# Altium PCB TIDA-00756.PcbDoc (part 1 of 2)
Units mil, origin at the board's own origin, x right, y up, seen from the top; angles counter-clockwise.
Board outline 4100 x 1700 mil, 4 copper layers (Top Layer, Signal Layer 1, Signal Layer 2, Bottom Layer), stack 43.668 mil thick; 130 components, 51 nets, 280 pads, 420 vias.
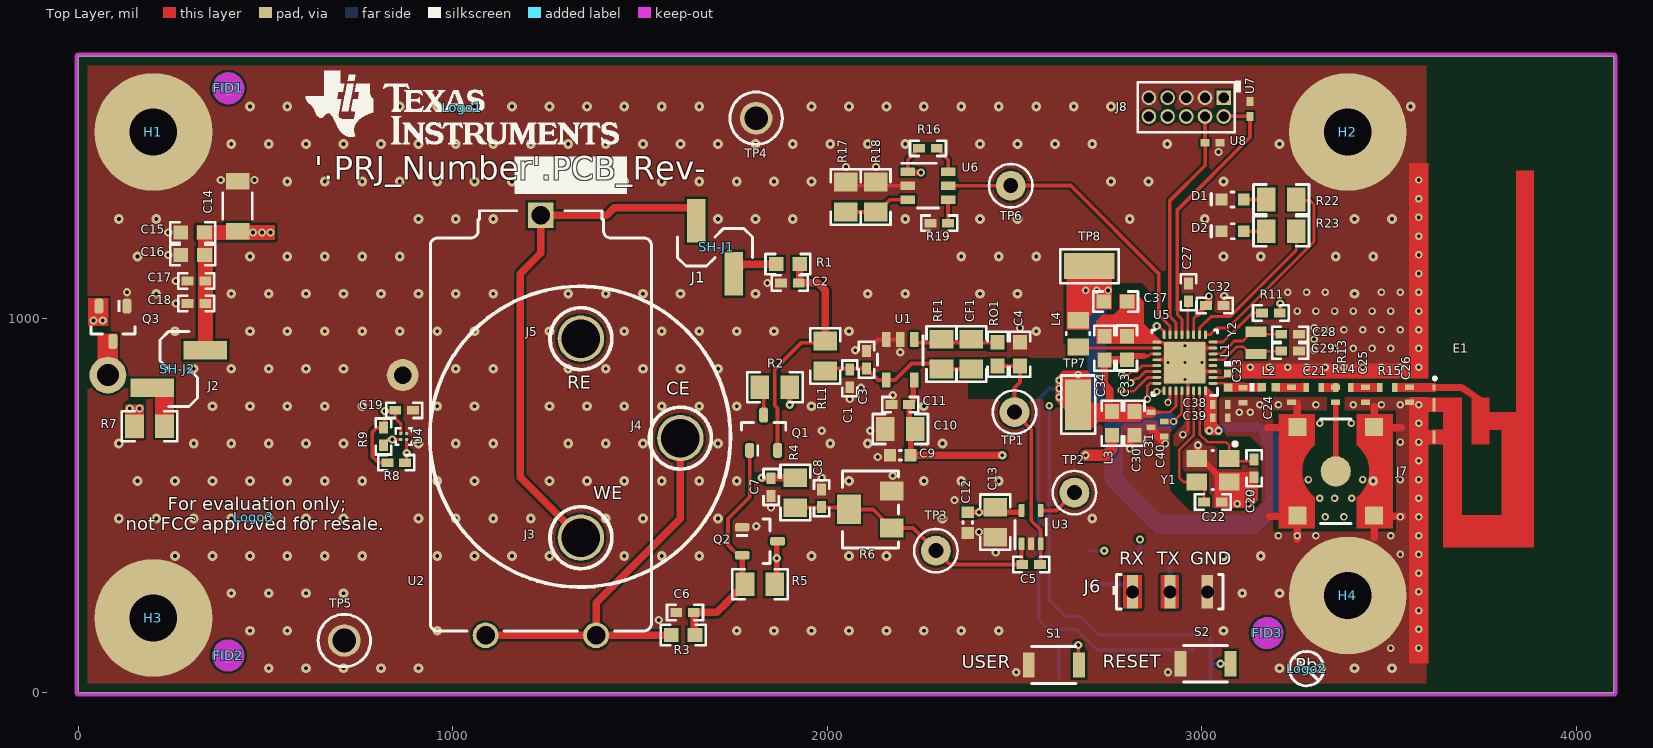
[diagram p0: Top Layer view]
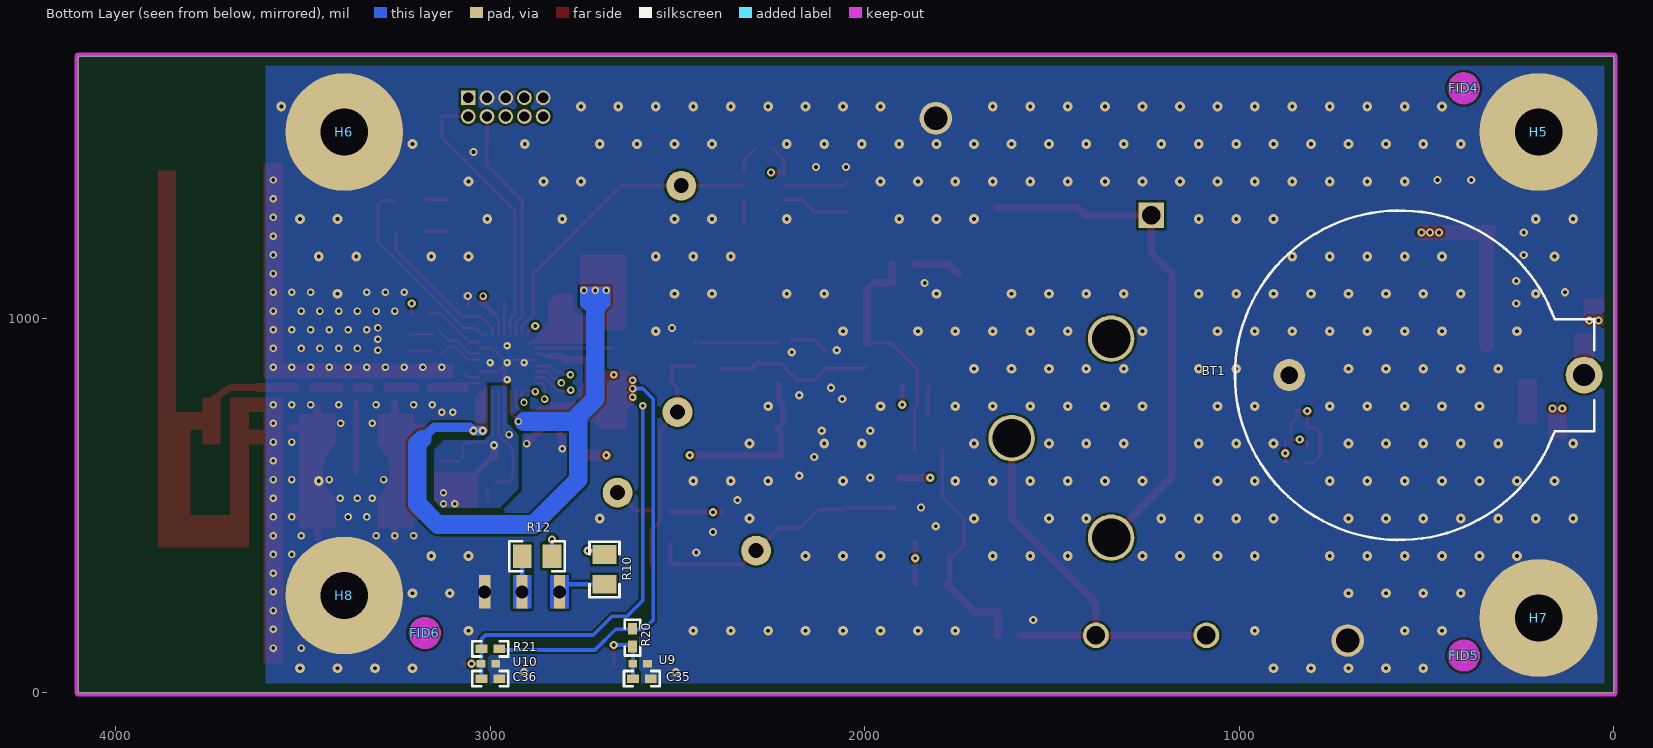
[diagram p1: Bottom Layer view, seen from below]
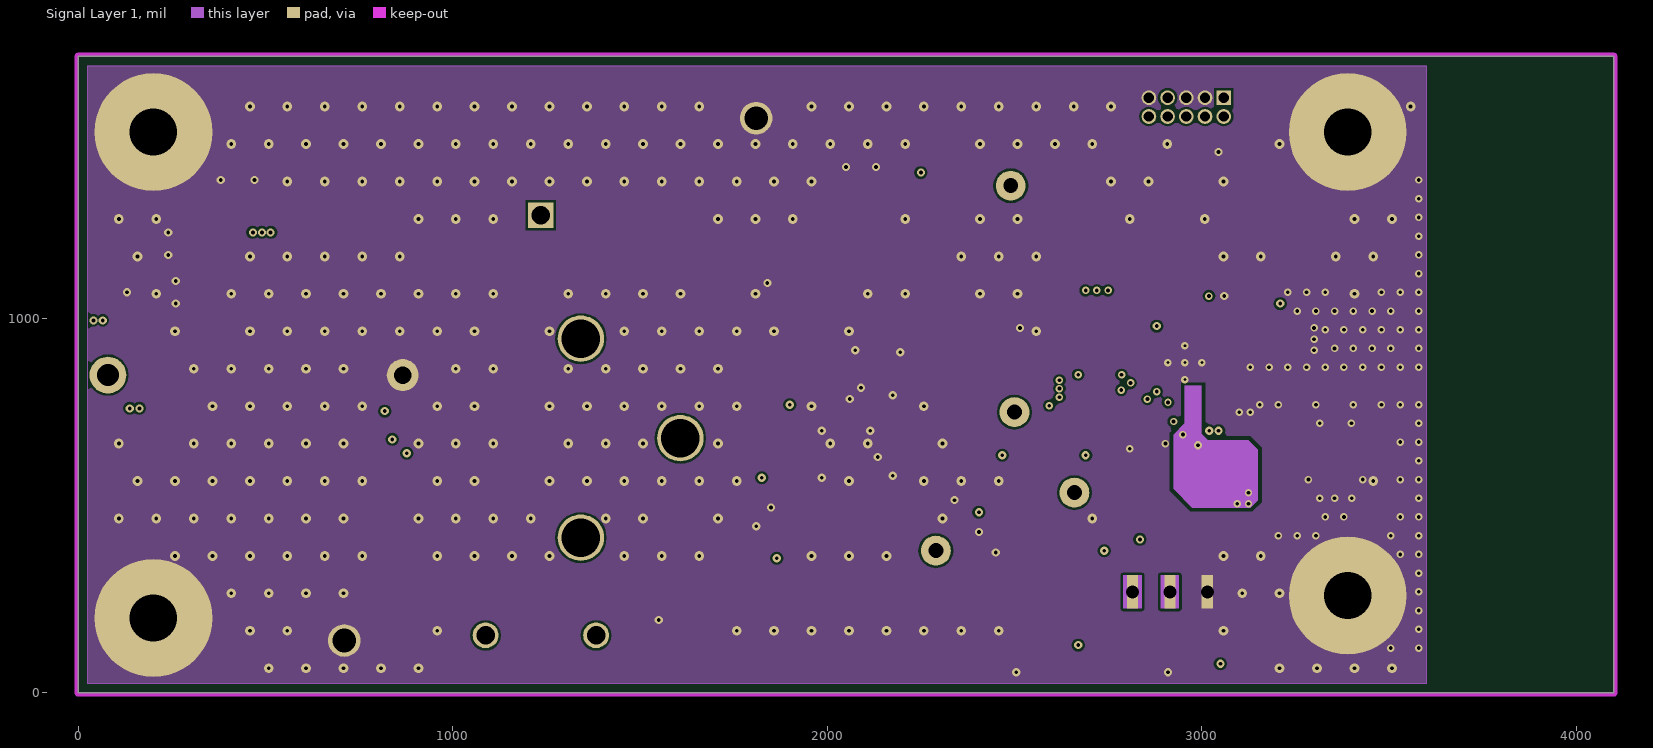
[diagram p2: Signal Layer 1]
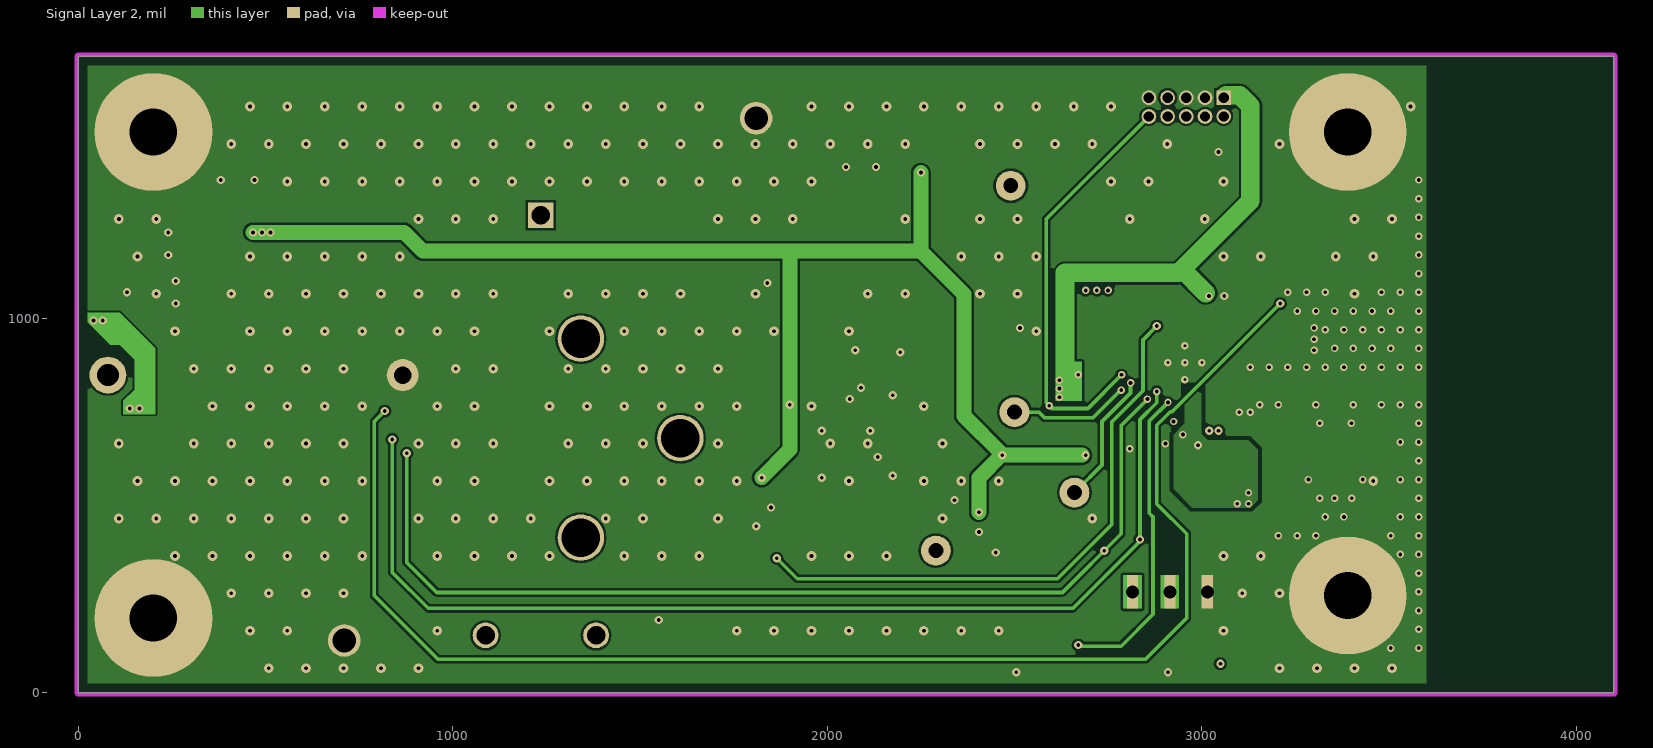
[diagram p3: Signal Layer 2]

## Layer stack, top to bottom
Top Solder: solder mask 0.4, Solder Resist, Dk 3.5
Top Layer: signal copper 1.417
Dielectric1: core 14, 370HR, Dk 4.2
Signal Layer 1: signal copper 1.417
Dielectric 2: prepreg 10, 370HR, Dk 4.2
Signal Layer 2: signal copper 1.417
Dielectric 3: core 14, 370HR, Dk 4.2
Bottom Layer: signal copper 1.417
Bottom Solder: solder mask 0.4, Solder Resist, Dk 3.5

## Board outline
0,0 4100,0 4100,1700 0,1700

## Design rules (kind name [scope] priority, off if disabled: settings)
AcuteAngle [All] p1: minimum=4.50000000000000E+0001 checktracksonly=FALSE
AssemblyTestPointUsage [All] p1: valid=2
BoardOutlineClearance BoardOutlineClearance_MountingHoles [OnCopper and InComponentClass('Mounting Holes')] p1: gap=40
BoardOutlineClearance BoardOutlineClearance_Poly [OnCopper and InPoly] p2: gap=25
BoardOutlineClearance [OnCopper and Not InComponentClass('Logo') and not InComponentClass('FiducialMark') and not InRegion(1000,500,4000,800)] p3: gap=25
Clearance Clearance_1 [IsRegion and InNet('GND')] p1: gap=6
Clearance Clearance_U4 [InComponent('U4')] p2: gap=6.6
Clearance Clearance_Keepouts [((IsTrack Or IsArc) And Not InPoly) And IsFree and IsKeepOut vs ((IsTrack Or IsArc) And Not InPoly) And IsFree and IsKeepOut] p3: gap=0
Clearance Clearance_Poly [InPolygon] p4: gap=12
Clearance [All] p5: gap=7.87
ComponentClearance ComponentClearance_sensor [InComponent('U1') vs InComponent('J2') or InComponent('J3')  or InComponent('J4')] p1: gap=0 collisioncheckmode=3 verticalgap=0 showdistances=FALSE
ComponentClearance ComponentClearance_RF [InComponent('R13') vs InComponent('R14')] p2: gap=0 collisioncheckmode=3 verticalgap=0 showdistances=FALSE
ComponentClearance ComponentClearance_MountingHoles_FiducialMarks [InComponentClass('Mounting Holes') vs InComponentClass('FiducialMark')] p3 off: gap=50 collisioncheckmode=3 verticalgap=10 showdistances=FALSE
ComponentClearance ComponentClearance_Shunt [InComponentClass('Header') vs InComponentClass('Shunt')] p4: gap=0 collisioncheckmode=3 verticalgap=0 showdistances=FALSE
ComponentClearance ComponentClearance_Logo [InComponentClass('Logo')] p5: gap=0 collisioncheckmode=3 verticalgap=0 showdistances=FALSE
ComponentClearance ComponentClearance_ScrewToNut [(HasFootprint('NY PMS 440 0025 PH')) vs (HasFootprint('Keystone_1902C'))] p6: gap=5 collisioncheckmode=3 verticalgap=10 showdistances=FALSE
ComponentClearance ComponentClearance_MountingHoles [InComponentClass('Mounting Holes')] p7 off: gap=250 collisioncheckmode=3 verticalgap=100000 showdistances=FALSE
ComponentClearance ComponentClearance_SmallPassives [HasFootprint('0201*') or HasFootprint('0402*') or HasFootprint('0508') or HasFootprint('0603*') or HasFootprint('0612') or HasFootprint('0805*') or HasFootprint('0815*') or HasFootprint('0830*') or HasFootprint('1206*') or HasFootprint('1210*') or HasFootprint('1808*') or HasFootprint('1812*') or HasFootprint('1825*') or HasFootprint('2010*') or HasFootprint('2220*') or HasFootprint('2225*') or HasFootprint('2512*') or HasFootprint('2728*') or HasFootprint('3518*') vs HasFootprint('0201*') or HasFootprint('0402*') or HasFootprint('0508') or HasFootprint('0603*') or HasFootprint('0612') or HasFootprint('0805*') or HasFootprint('0815*') or HasFootprint('0830*') or HasFootprint('1206*') or HasFootprint('1210*') or HasFootprint('1808*') or HasFootprint('1812*') or HasFootprint('1825*') or HasFootprint('2010*') or HasFootprint('2220*') or HasFootprint('2225*') or HasFootprint('2512*') or HasFootprint('2728*') or HasFootprint('3518*')] p8: gap=5 collisioncheckmode=3 verticalgap=5 showdistances=FALSE
ComponentClearance ComponentClearance_THtoSMT [IsThruComponent vs IsSMTComponent] p9: gap=5 collisioncheckmode=3 verticalgap=5 showdistances=FALSE
ComponentClearance ComponentClearance_THtoTH [IsThruComponent vs IsThruComponent] p10: gap=5 collisioncheckmode=3 verticalgap=5 showdistances=FALSE
ComponentClearance [All] p11: gap=5 collisioncheckmode=3 verticalgap=5 showdistances=FALSE
DiffPairsRouting [All] p1: maxlimit=100 minlimit=10 mostfreqgap=10 toplayer_minwidth=15 toplayer_maxwidth=15 toplayer_prefwidth=15 midlayer1_minwidth=15 midlayer1_maxwidth=15 midlayer1_prefwidth=15 midlayer2_minwidth=15 midlayer2_maxwidth=15 midlayer2_prefwidth=15 bottomlayer_minwidth=15 bottomlayer_maxwidth=15 bottomlayer_prefwidth=15 maxuncoupledlength=1000
FabricationTestPointUsage TestPointUsage [All] p1: valid=2 allowmultiple=FALSE
FabricationTestpoint Testpoint [All] p1: side=3 testpointundercomponent=TRUE minsize=40 maxsize=100 preferedsize=60 minholesize=0 maxholesize=40 preferedholesize=32 testpointgrid=1 allowsidetop=TRUE allowsidebottom=TRUE usegrid=TRUE gridtolerance=0.01
FanoutControl Fanout_LCC [IsLCC] p1: bgadir=Out bgaviamode=Centered fanoutstyle=Auto fanoutdirection=Alternating viagrid=1 // Fanout_LCC (Default Rule)
FanoutControl Fanout_BGA [IsBGA] p2: bgadir=Out bgaviamode=Centered fanoutstyle=Auto fanoutdirection=Alternating viagrid=1 // Fanout_BGA (Default Rule)
FanoutControl Fanout_Default [All] p4: bgadir=Out bgaviamode=Centered fanoutstyle=Auto fanoutdirection=Alternating viagrid=1 // Fanout_Default (Default Rule)
FanoutControl Fanout_Small [(CompPinCount < 5)] p5: bgadir=Out bgaviamode=Centered fanoutstyle=Auto fanoutdirection=OutThenIn viagrid=1 // Fanout_Small (Default Rule)
HoleSize [All] p1: absolutevalues=TRUE maxlimit=251 minlimit=7.87 maxpercent=80.000 minpercent=20.000
MinimumAnnularRing MinimumAnnularRing_1 [InComponent('J6')] p1: minimumring=0
MinimumAnnularRing MinimumAnnularRing_ThermalPadVias [IsVia and InAnyComponent] p2: minimumring=5.91
MinimumAnnularRing [All] p3: minimumring=5
MinimumSolderMaskSliver MinimumSolderMaskSliver_Logo [InComponentClass('Logo') vs InComponentClass('Logo')] p1: minsoldermaskwidth=0.7
MinimumSolderMaskSliver [All] p2: minsoldermaskwidth=3.94
PlaneConnect [All] p1: planeconnectstyle=Relief reliefexpansion=10 reliefentries=4 reliefconductorwidth=10 reliefairgap=10
PolygonConnect PolygonConnect_TR [incomponent('Q1') or incomponent('J5')] p1: connectstyle=Relief reliefconductorwidth=12 reliefentries=4 polygonreliefangle="90 Angle" airgapwidth=10
PolygonConnect [All] p2: connectstyle=Direct reliefconductorwidth=10 reliefentries=4 polygonreliefangle="90 Angle" airgapwidth=10
RoutingVias ThermalPadVias [IsVia and InAnyComponent] p1: holewidth=7.87 width=19.68 viastyle="Through Hole" minholewidth=7.87 minwidth=19.68 maxholewidth=12.99 maxwidth=23.62
RoutingVias [All] p2: holewidth=16 width=26 viastyle="Through Hole" minholewidth=7.87 minwidth=20 maxholewidth=40 maxwidth=65
SilkToBoardRegionClearance [Not ((IsComment or IsDesignator) And (Hide <> 'False')) and not InRegion(1000,500,4000,800)] p1:
SilkToSilkClearance SilkToSilkClearance_Pb-FreeLogo [(HasFootprint('Pb-Free_Overlay_Medium') OR HasFootprint('Pb-Free_Overlay_Small')) vs (HasFootprint('Pb-Free_Overlay_Medium') OR HasFootprint('Pb-Free_Overlay_Small'))] p1: silktosilkclearance=0
SilkToSilkClearance [All] p2: silktosilkclearance=4
SilkToSolderMaskClearance SilkToComponentPadClearance [IsPad and InAnycomponent] p1: minsilkscreentomaskgap=5 clearancetoexposedcopper=TRUE
SilkToSolderMaskClearance "Silk to Solder Mask Opening" [All] p2: minsilkscreentomaskgap=4 clearancetoexposedcopper=FALSE
SolderMaskExpansion [All] p1: expansion=1.8
Width [All] p1: maxlimit=100 minlimit=6 preferedwidth=10 checkconnectedcopper=TRUE
15 further rules are at their usual default settings.

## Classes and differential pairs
component class Shunt: SH-J1 SH-J2
component class TIDA-00756_MCU: C19 C20 C21 C22 C23 C24 C25 C26 C27 C28 C29 C30 C31 C32 C33 C34 C35 C36 C37 C38 C39 C40 D1 D2 E1 J6 J7 J8 L1 L2 L3 L4 R8 R9 R10 R11 R12 R13 R14 R15 R16 R17 R18 R19 R20 R21 R22 R23 S1 S2 TP6 TP7 TP8 U4 U5 U6 U7 U8 U9 U10 Y1 Y2
component class TIDA-00756_CO_Sensor: BT1 C1 C2 C3 C4 C5 C6 C7 C8 C9 C10 C11 C12 C13 C14 C15 C16 C17 C18 CF1 J1 J2 J3 J4 J5 Q1 Q2 Q3 R1 R2 R3 R4 R5 R6 R7 RF1 RL1 RO1 TP1 TP2 TP3 TP4 TP5 U1 U2 U3
component class Header: J1 J2 J6 J8
component class "Mounting Holes": H1 H2 H3 H4
component class Logo: Logo1
component class TIDA-00756_Hardware: FID1 FID2 FID3 FID4 FID5 FID6 H1 H2 H3 H4 H5 H6 H7 H8 Logo1 Logo2 Logo3 SH-J1 SH-J2 ZZ2 ZZ3 ZZ4
component class FiducialMark: FID1 FID2 FID3 FID4 FID5 FID6
component class AssemblyNote: ZZ2 ZZ3 ZZ4

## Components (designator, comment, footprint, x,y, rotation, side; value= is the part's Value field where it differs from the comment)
BT1 "BS-7" BAT_BS-7 472.44,848.98 r0 bottom locked
C1 "CC0402JRNPO9BN150" 0402 2060,840 r90 top
C2 "CC0402JRNPO9BN150" 0402 1900,1095 r180 top
C3 "CC0402JRNPO9BN150" 0402 2105,890 r90 top
C4 "C1608X5R1E105K080AC" 0603 2515,905 r90 top
C5 "C0402C102J3RACTU" 0402 2544.5,343 r180 top
C6 "CC0402JRNPO9BN150" 0402 1620,215 r180 top
C7 "CC0402JRNPO9BN150" 0402 1850,550 r270 top
C8 "C1005X7R1H104K" 0402 1985,520 r90 top
C9 "C0603C104K8RACTU" 0603L 2195,635 r0 top
C10 "C2012X5R0J106M" 0805_HV 2195,705 r0 top
C11 "CC0402JRNPO9BN150" 0402 2195,770 r180 top
C12 "C0603C104K8RACTU" 0603L 2375,455 r90 top
C13 "C2012X5R0J106M" 0805_HV 2449,456 r90 top
C14 "C3216X5R1A107M160AC" 1206_190 425,1300 r90 top
C15 "C1608X5R0J106M" 0603 305,1230 r180 top
C16 "C1608X7R1C105K" 0603 305,1170 r180 top
C17 "C1005X7R1H104K050BB" 0402 315,1100 r180 top
C18 "C1005X7R1C103K050BA" 0402 315,1040 r180 top
C19 "GRM155R71C103KA01D" 0402 870,755 r0 top
C20 "GRM1555C1E120JA01D" 0402 3140,600 r90 top
C21 "GRM1555C1H120JA01D" 0402S 3299,816.3 r180 top
C22 "GRM1555C1E120JA01D" 0402 3030,510 r180 top
C23 "GRM1555C1H1R2BA01D" 0402S 3110,795 r270 top
C24 "GRM1555C1H1R2BA01D" 0402S 3240,796.3 r270 top
C25 "Used in BOM report" 0402S 3437,796.3 r90 top
C26 "Used in BOM report" 0402S 3555,796.3 r90 top
C27 "GRM155R61A105KE15D" 0402 2965,1070 r90 top
C28 "GRM1555C1E120JA01D" 0402 3236,958 r0 top
C29 "GRM1555C1E120JA01D" 0402 3236,913 r0 top
C30 "Used in BOM report" 0603 2820,720 r270 top
C31 "GRM155R70J104KA01D" 0402S 2865,730 r270 top
C32 "GRM155R70J104KA01D" 0402 3035,1035 r0 top
C33 "GRM188R60J106ME47D" 0603 2800,921.31 r270 top
C34 "GRM188R71E104KA01D" 0603 2740,921 r270 top
C35 "C1005X7R1H222K" 0402 2595,38 r0 bottom
C36 "C1005X7R1H222K" 0402 3000,38 r0 bottom
C37 "GRM188R60J106ME47D" 0603 2770,1045 r180 top
C38 "GRM155R70J104KA01D" 0402S 3050,770 r0 top
C39 "GRM155R70J104KA01D" 0402S 3050,735 r0 top
C40 "Used in BOM report" 0402S 2900,705 r270 top
CF1 "08053C104KAT2A" 0805_HV 2385,905 r270 top
D1 "LS L29K-G1J2-1-Z" "LS L29K_Red" 3082.56,1317.87 r180 top
D2 "LY L29K-H1K2-26-Z" "LY L29K_Yellow" 3082.56,1232.87 r180 top
E1 "ANTENNA_DN007A" ANTENNA_DN007A 3620.31,816.03 r270 top net-tie
FID1 "Fiducial" Fiducial10-20 400,1615 r0 top
FID2 "Fiducial" Fiducial10-20 400,100 r0 top
FID3 "Fiducial" Fiducial10-20 3175,160 r0 top
FID4 "Fiducial" Fiducial10-20 400,1615 r90 bottom
FID5 "Fiducial" Fiducial10-20 400,100 r90 bottom
FID6 "Fiducial" Fiducial10-20 3175,160 r90 bottom
H1 "NY PMS 440 0025 PH" "NY PMS 440 0025 PH" 200,1497.95 r0 top locked
H2 "NY PMS 440 0025 PH" "NY PMS 440 0025 PH" 3390,1497.95 r0 top locked
H3 "NY PMS 440 0025 PH" "NY PMS 440 0025 PH" 200,200 r0 top locked
H4 "NY PMS 440 0025 PH" "NY PMS 440 0025 PH" 3390,260 r0 top locked
H5 "1902C" Keystone_1902C 200,1497.95 r180 bottom locked
H6 "1902C" Keystone_1902C 3390,1497.95 r180 bottom locked
H7 "1902C" Keystone_1902C 200,200 r180 bottom locked
H8 "1902C" Keystone_1902C 3390,260 r180 bottom locked
J1 "87898-0204" Molex_87898-0204 1700,1190 r0 top
J2 "87898-0204" Molex_87898-0204 267.72,865 r90 top
J3 "2-50871-2" TE_2-50871-2 1341.93,414.68 r0 top
J4 "2-50871-2" TE_2-50871-2 1607.68,680.43 r0 top
J5 "2-50871-2" TE_2-50871-2 1341.93,946.18 r270 top
J6 "5-146280-3" TE_5-146280-3 2915,270 r0 top
J7 "CONSMA001-SMD-G" Linx_CONSMA001-SMD-G 3358,592 r0 top
J8 "GRPB052VWVN-RC" CONN_GRPB052VWVN-RC 2958.94,1564.69 r180 top
L1 "LQG15HS15NJ02D" IND_LQG15H 3071,835 r270 top
L2 "LQG15HS2N0S02D" IND_LQG15H 3179,816.3 r0 top
L3 "BLM18HE152SN1D" 0603 2760,720 r90 top
L4 "CKS2125100M-T" 0805_145 2670,960 r90 top
Logo1 "Texas Instruments" TI_Stacked_Overlay_Small 1025,1563 r0 top
Logo2 "Pb-Free Symbol" Pb-Free_Overlay_Small 3280,65 r0 top
Logo3 "FCC disclaimer" FCC_disclaimer_stacked 468,469 r0 top
Q1 "MMBFJ270" SOT-23 1830,695 r90 top
Q2 "MMBFJ270" SOT-23 1820,405 r0 top
Q3 "SI2323DS" SOT-23 92,986 r270 top
R1 "CRCW06030000Z0EA" 0603 1895,1145 r0 top
R2 "CRCW08052M00JNEA" 0805_HV 1860,816.12 r180 top
R3 "CRCW06030000Z0EA" 0603 1615,155 r0 top
R4 "ERJ-6GEYK226V" 0805_HV 1915,535 r90 top
R5 "CRCW08052M55FKEA" 0805_HV 1820,290 r0 top
R6 "3224W-1-205E" TRIM_3224W 2115,490 r180 top
R7 "CRCW08050000Z0EA" 0805_HV 190,712 r0 top
R8 "CRCW04024K75FKED" 0402 848.7,614.92 r180 top
R9 "CRCW04024K75FKED" 0402 815,685 r90 top
R10 "CRCW08050000Z0EA" 0805_HV 2695,330 r90 bottom
R11 "CRCW04020000Z0ED" 0402 3185,1015 r0 top
R12 "CRCW08050000Z0EA" 0805_HV 2875,365 r180 bottom
R13 "CRCW04020000Z0ED" 0402S 3358,796 r270 top
R14 "CRCW04020000Z0ED" 0402S 3378,816 r0 top
R15 "CRCW04020000Z0ED" 0402S 3496,816.3 r0 top
R16 "CRCW04020000Z0ED" 0402 2268.94,1454.69 r180 top
R17 "ERJ-6ENF5492V" 0805_HV 2048.94,1324.69 r270 top
R18 "ERJ-6ENF1963V" 0805_HV 2128.94,1324.69 r90 top
R19 "CRCW040210K0FKED" 0402 2298.94,1254.69 r0 top
R20 "CRCW040247K5FKED" 0402 2620,148 r90 bottom
R21 "CRCW040247K5FKED" 0402 3000,118 r180 bottom
R22 "CRCW0805442RFKEA" 0805_HV 3212.44,1317.87 r180 top
R23 "CRCW0805487RFKEA" 0805_HV 3212.44,1232.87 r180 top
RF1 "CRCW08051M78FKEA" 0805_HV 2305,905 r90 top
RL1 "CRCW08050000Z0EA" 0805_HV 1995,900 r270 top
RO1 "CRCW060349K9FKEA" 0603 2455,905 r270 top
S1 "B3U-1000P" SW_B3U-1000P 2605,75 r0 top
S2 "B3U-1000P" SW_B3U-1000P 3010,78 r0 top
SH-J1 "969102-0000-DA" SNT-100-BK-G 1705,1190 r0 top
SH-J2 "969102-0000-DA" SNT-100-BK-G 265,865 r90 top
TP1 "5004" Keystone5004 2500,750 r180 top
TP2 "5004" Keystone5004 2660,535 r180 top
TP3 "5004" Keystone5004 2290,380 r0 top
TP4 "5011" Keystone5011 1810,1535 r0 top
TP5 "5011" Keystone5011 710,140 r0 top
TP6 "5004" Keystone5004 2490,1354.69 r0 top
TP7 "5015" Testpoint_Keystone_Miniature 2670,770 r90 top
TP8 "5015" Testpoint_Keystone_Miniature 2700,1140 r0 top
U1 "LPV811DBVR" DBV0005A_N 2195,890 r270 top
U2 "TGS5342" FIGARO_TGS5342 1235,715 r270 top
U3 "TLV3691IDCKR" DCK0005A_N 2544.5,443 r90 top
U4 "TMP103AYFFR" YFF0004AAAA 868.7,684.92 r0 top
U5 "CC2650F128RSMR" RSM0032B 2955,882 r180 top
U6 "TPL5111DDCR" DDC0006A_N 2268.94,1354.69 r0 top
U7 "TPD1E10B06DPYR" DPY0002A 3128.94,1559.69 r90 top
U8 "TPD1E10B06DPYR" DPY0002A 3028.94,1469.69 r0 top
U9 "TPD1E10B06DPYR" DPY0002A 2600,78 r180 bottom
U10 "TPD1E10B06DPYR" DPY0002A 3005,78 r180 bottom
Y1 "TSX-3225 24.0000MF20G-AC3" EPSON_TSX-3225 3030,595 r270 top
Y2 "FC-12M 32.7680KA-A3" Epson_FC-12M 3145,935 r90 top
ZZ2 "These assemblies are ESD sensitive, ESD precautions shall be observed." AssemblyNote 185,3829.11 r0 top
ZZ3 "These assemblies must be clean and free from flux and all contaminants. Use of no clean flux is not acceptable." AssemblyNote 185,3740.56 r0 top
ZZ4 "These assemblies must comply with workmanship standards IPC-A-610 Class 2, unless otherwise specified." AssemblyNote 185,3652 r0 top

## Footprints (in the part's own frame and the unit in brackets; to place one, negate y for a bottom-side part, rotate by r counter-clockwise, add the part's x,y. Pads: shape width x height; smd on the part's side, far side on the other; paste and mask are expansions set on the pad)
0402 [mm] "0402 from SM-752 data"
  rect 0.8x0.6 smd: 1(-0.6,0) 2(0.6,0)
  silkscreen extent -1.22,-0.52 1.22,0.52, body extent -0.55,-0.3 0.55,0.3, height 0.6
0402S [mil] "Based on C0402S footprint from PADS legacy"
  rect 15x24 smd: 1(-20,0) 2(20,0)
  body extent -22,-12 22,12, height 24
0603 [mm] "0603 from SM-752 data"
  rect 1x0.95 smd: 1(-0.8,0) 2(0.8,0)
  silkscreen extent -1.52,-0.69 1.52,0.69, body extent -0.87,-0.47 0.87,0.47, height 1
0603L [mm] "0603 from SM-752 data"
  rect 0.8x0.85 smd: 1(-0.7,0) 2(0.7,0)
  silkscreen extent -0.07,-0.33 0.07,0.33, body extent -0.87,-0.47 0.87,0.47, height 1
0805_145 [mm] "0805 / 1.45mm height"
  rect 1.15x1.45 smd: 1(-0.9,0) 2(0.9,0)
  silkscreen extent -0.1,-0.8 0.1,0.8, body extent -1.1,-0.72 1.1,0.72, height 1.45
0805_HV [mil] "0805 with 30mil clearance between pads"
  rect 50x63 smd: 1(-40,0) 2(40,0)
  silkscreen extent -74,-40 74,40, body extent -43,-29 43,29, height 57
1206_190 [mm] "1206_190"
  rect 1.1x1.6 smd: 1(-1.7,0) 2(1.7,0)
  silkscreen extent -0.9,-1 0.9,1, body extent -1.75,-0.95 1.75,0.95, height 1.9
ANTENNA_DN007A [mm] "SMD, 3-Leads"
  rect 0.4x0.2 smd paste-2 mask-2: 1(0,0)
  rect 0.9x0.2 smd paste-2 mask-2: 2(1.18,-0.01) 3(3.37,0)
  Top Layer region: 10.84,0.63 10.84,6.775 -14.715,6.775 -14.715,5.59 1.685,5.59 1.685,3.765 0.685,3.765 0.685,3.271 -0.225,1.951 -0.225,-0.11 0.21,-0.11 0.21,1.816 0.737,2.58 3.86,2.58 3.86,3.765 2.86,3.765 2.86,4.59 8.685,4.59 8.685,1.895 0.685,1.895 0.685,-0.11 1.66,-0.11 1.66,0.63 2.885,0.63 2.885,-0.11 3.86,-0.11 3.86,0.63
  silkscreen extent -0.71,-0.04 -0.51,0.16
AssemblyNote [mil] "Assembly Note"
BAT_BS-7 [mm] "Memory Protection Devices CR2032 battery holder"
  round 2.5 hole 1.5: 1(-10,0)
  round 2.17 hole 1.181: 2(10,0)
  silkscreen extent -10.7,-11.16 13.68,11.18, body extent -10.69,-11.17 13.7,11.17, height 9.02
CONN_GRPB052VWVN-RC [mm] "SULLINS"
  rect 1x1 hole 0.7 mask+0.08: 1(-2.54,-0.635)
  round 1 hole 0.7 mask+0.08: 2(-2.54,0.635) 3(-1.27,-0.635) 4(-1.27,0.635) 5(0,-0.635) 6(0,0.635) 7(1.27,-0.635) 8(1.27,0.635) 9(2.54,-0.635) 10(2.54,0.635)
  silkscreen extent -3.7,-1.8 3.3,1.7, body extent -3.17,-1.7 3.17,1.7, height 4
DBV0005A_N [mm] "SOT23, 5-Leads, Body 2.9x1.6mm, Pitch 0.95mm, Lead Span 2.8mm, IPC Medium Density"
  rrect17% 1x0.6 smd: 1(-1.375,0.95) 2(-1.375,0) 3(-1.375,-0.95) 4(1.375,-0.95) 5(1.375,0.95)
  silkscreen extent -1.63,-1.55 0.38,1.55, body extent -1.42,-1.46 1.42,1.46, height 1.09
DCK0005A_N [mm] "SOT353, 5-Leads, Body 2x1.3mm, Pitch 0.65mm, Lead Span 2.1mm, IPC Medium Density"
  rrect25% 0.85x0.4 smd: 1(-1.125,0.65) 2(-1.125,0) 3(-1.125,-0.65) 4(1.125,-0.65) 5(1.125,0.65)
  silkscreen extent -1.48,-1.02 0.55,1.1, body extent -1.14,-1 1.14,1, height 0.95
DDC0006A_N [mm]
  rrect17% 1x0.6 smd: 1(-1.375,0.95) 2(-1.375,0) 3(-1.375,-0.95) 4(1.375,-0.95) 5(1.375,0) 6(1.375,0.95)
  silkscreen extent -1.75,-1.52 0.7,1.53, body extent -1.43,-1.48 1.43,1.49, height 0.92
DPY0002A [mm] "R-PX2SON-N2"
  rect 0.6x0.5 smd: 1(-0.5,0) 2(0.5,0)
  body extent -0.55,-0.35 0.55,0.35, height 0.4
Epson_FC-12M [mm] "Epson"
  rect 0.7x1.4 smd: 1(-0.75,0) 2(0.75,0)
  body extent -1.05,-0.63 1.05,0.63, height 0.6
EPSON_TSX-3225 [mm] "SMD, 4-Leads, Body 2.65x3.35mm, Height 0.6mm"
  rect 1.15x1.4 smd: 1(-0.8,1.1) 2(-0.8,-1.1) 3(0.8,-1.1) 4(0.8,1.1)
  silkscreen extent -1.9,-0.05 1.33,1.63, body extent -1.33,-1.68 1.33,1.68, height 0.61
FCC_disclaimer_stacked [mil]
Fiducial10-20 [mm]
  round 1 smd mask+0.5: 1(0,0)
  Top Layer keep-out circle w1.178: c0,0 r0.5
FIGARO_TGS5342 [mm] "TH, 3-Leads, Body 15x27.9mm, Pin Spacing 25.5mm"
  rect 1.75x1.75 hole 1.25: 1(-14.25,0)
  round 1.75 hole 1.25: 2(14.25,-3.75) 2(14.25,3.75)
  silkscreen extent -14.55,-7.5 13.95,7.5, body extent -14.55,-7.5 14.55,7.5, height 16.9
IND_LQG15H [mm] "MuRata"
  rect 0.55x0.6 smd: 1(-0.475,0) 2(0.475,0)
  silkscreen extent -1.3,-0.3 -0.95,0.3, body extent -0.52,-0.27 0.52,0.27, height 0.55
Keystone5004 [mil] "For Keystone 500x miniature loop terminals"
  round 80 hole 40: 1(0,0)
  silkscreen extent -58,-58 58,58, body extent -49,-49 49,49, height 182
Keystone5011 [mil] "Keystone Multipurpose loops"
  round 87 hole 63: 1(0,0)
  silkscreen extent -70,-70 70,70, body extent -63,-63 63,62, height 319
Keystone_1902C [mil] "Hex Standoff, 4-40 threaded, nylon"
  body extent -145,-126 146,126, height 501
Linx_CONSMA001-SMD-G [mm] "SMD, 5-Leads, Body 7x7mm, Height 10.5mm"
  round 2.05 smd: 1(0,0)
  rect 1.2x1.2 smd: 2(-2.6,-3) 3(2.6,-3) 4(2.6,3) 5(-2.6,3)
  Top Layer region: 3.88,-3.88 1.44,-3.88 1.44,-1.761 1.448,-1.761 2.062,-0.974 2.28,0 2.062,0.974 1.448,1.761 1.448,1.761 1.44,1.761 1.44,3.88 3.88,3.88
  Top Layer region: -3.88,-3.88 -1.44,-3.88 -1.44,-1.761 -1.448,-1.761 -2.062,-0.974 -2.28,0 -2.062,0.974 -1.448,1.761 -1.448,1.761 -1.44,1.761 -1.44,3.88 -3.88,3.88
  silkscreen extent -1.04,-3.55 1.04,3.55, body extent -3.55,-3.55 3.55,3.55, height 10.5
"LS L29K_Red" [mm] "SMD, 2-Leads, Body 1.3x0.8mm"
  rect 0.8x0.8 smd paste-0.4: 1(-0.75,0) 2(0.75,0)
  silkscreen extent -0.1,-0.5 1.45,0.5, body extent -0.9,-0.45 0.9,0.45, height 0.67
"LY L29K_Yellow" [mm] "OSRAM"
  rect 0.8x0.8 smd paste-0.4: 1(-0.75,0) 2(0.75,0)
  silkscreen extent -0.1,-0.5 1.45,0.5, body extent -0.9,-0.45 0.9,0.45, height 0.67
Molex_87898-0204 [mm] "Header, 2.54 mm, 2x1, R/A, SMT"
  rect 1.27x2.96 smd: 1(-1.27,1.8) 2(1.27,-1.8)
  silkscreen extent -2.54,-1.27 2.54,1.27, body extent -2.54,-2.4 2.54,2.4, height 9.65
"NY PMS 440 0025 PH" [mm] "4-40 nylon screw and mounting hole"
  round 8 hole 3.2: 1(0,0)
  body extent -3.3,-3.3 3.3,3.3, height 2.69
Pb-Free_Overlay_Small [mil]
  silkscreen extent -46,-46 46,46
RSM0032B [mm] "QFN, 32-Leads, Body 4x4mm, Pitch 0.4mm, Thermal Pad 2.8x2.8mm, TI Recommended"
  oval 0.6x0.2 smd: 1(-1.9,1.4) 2(-1.9,1) 3(-1.9,0.6) 4(-1.9,0.2) 5(-1.9,-0.2) 6(-1.9,-0.6) 7(-1.9,-1) 8(-1.9,-1.4) 17(1.9,-1.4) 18(1.9,-1) 19(1.9,-0.6) 20(1.9,-0.2) 21(1.9,0.2) 22(1.9,0.6) 23(1.9,1) 24(1.9,1.4)
  oval 0.2x0.6 smd: 9(-1.4,-1.9) 10(-1,-1.9) 11(-0.6,-1.9) 12(-0.2,-1.9) 13(0.2,-1.9) 14(0.6,-1.9) 15(1,-1.9) 16(1.4,-1.9) 25(1.4,1.9) 26(1,1.9) 27(0.6,1.9) 28(0.2,1.9) 29(-0.2,1.9) 30(-0.6,1.9) 31(-1,1.9) 32(-1.4,1.9)
  rect 2.8x2.8 smd paste-1.4: 33(0,0)
  silkscreen extent -2.23,-2.23 2.23,2.23, body extent -2.07,-2.07 2.08,2.08, height 1.01
SNT-100-BK-G [mil] "Samtec STEP model"
  round 1 on Mech3: 0(0,0)
  body extent -100,-50 100,50, height 344
SOT-23 [mm] "SOT23, 3-Leads, Body 2.9x1.3mm, Pitch 0.95mm, Lead Span 2.5mm, IPC Medium Density"
  rrect50% 1x0.6 smd: 1(-1.2,0.95) 2(-1.2,-0.95) 3(1.2,0)
  silkscreen extent -1.63,-1.5 0.7,1.5, body extent -1.16,-1.45 1.21,1.45, height 1
SW_B3U-1000P [mm] "OMRON"
  rect 0.8x1.7 smd: 1(-1.7,0) 2(1.7,0)
  silkscreen extent -1.5,-1.25 1.5,1.25, body extent -1.5,-1.25 1.5,1.25, height 1.75
TE_2-50871-2 [mm] "CONN SOCKET RCPT .056-.065 30AU, TH"
  round 3.15 hole 2.62: 1(0,0)
  silkscreen extent -2.1,-2.1 2.1,2.1, body extent -1.46,-1.46 1.46,1.46, height 0.46
TE_5-146280-3 [mm] "Header, 2.54mm, 3x1, TH"
  rect 0.76x2.29 hole 0.89: 1(-2.54,0) 2(0,0) 3(2.54,0)
  silkscreen extent -3.9,-1.17 3.61,1.17, body extent -3.61,-1.17 3.61,1.17, height 8.13
Testpoint_Keystone_Miniature [mil] "Miniature SMT test point"
  rect 135x70 smd: 1(0,0)
  silkscreen extent -78,-46 78,45, body extent -52,-20 52,20, height 61
TI_Stacked_Overlay_Small [mil]
  silkscreen extent -418,-98 418,98
TRIM_3224W [mm] "BOURNS"
  rect 1.6x1.3 smd: 1(-1.45,1.25) 3(-1.45,-1.25)
  rect 1.6x2 smd: 2(1.45,0)
  silkscreen extent -1.9,-2.6 1.9,2.6, body extent -1.8,-2.5 1.8,2.5, height 5.31
YFF0004AAAA [mm] "TI DSBGA 0.790x0.790mm"
  round 0.23 smd paste-0.13 mask+0.03: A1(-0.2,0.2) A2(0.2,0.2) B1(-0.2,-0.2) B2(0.2,-0.2)
  silkscreen extent -0.55,-0.55 0.55,0.55, body extent -0.39,-0.39 0.39,0.39, height 0.63

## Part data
BT1: "Battery Holder, CR2032, Retainer clip, TH"
C1 C2 C3 C6 C7 C11: "CAP, CERM, 15 pF, 50 V, +/- 5%, C0G/NP0, 0402"
C4: "CAP, CERM, 1 µF, 25 V, +/- 10%, X5R, 0603"
C5: "CAP, CERM, 1000 pF, 25 V, +/- 5%, X7R, 0402"
C8 C17: "CAP, CERM, 0.1 µF, 50 V, +/- 10%, X7R, 0402"
C9 C12: "CAP, CERM, 0.1 µF, 10 V, +/- 10%, X7R, 0603"
C10 C13: "CAP, CERM, 10 µF, 6.3 V, +/- 20%, X5R, 0805"
C14: "CAP, CERM, 100 µF, 10 V, +/- 20%, X5R, 1206_190"
C15 C33 C37: "CAP, CERM, 10 µF, 6.3 V, +/- 20%, X5R, 0603"
C16: "CAP, CERM, 1 µF, 16 V, +/- 10%, X7R, 0603"
C18 C19: "CAP, CERM, 0.01 µF, 16 V, +/- 10%, X7R, 0402"
C20 C22 C28 C29: "CAP, CERM, 12 pF, 25 V, +/- 5%, C0G/NP0, 0402"
C21: "CAP, CERM, 12 pF, 50 V, +/- 5%, C0G/NP0, 0402"
C23 C24: "CAP, CERM, 1.2 pF, 50 V, +/- 8.3%, C0G/NP0, 0402"
C25 C26 C30 C40: library part Capacitor, "CAP, CERM, xxxF, xxV, [TempCo], xx%, [PackageReference]"
C27: "CAP, CERM, 1 µF, 10 V, +/- 10%, X5R, 0402"
C31 C32 C38 C39: "CAP, CERM, 0.1 µF, 6.3 V, +/- 10%, X7R, 0402"
C34: "CAP, CERM, 0.1 µF, 25 V, +/- 10%, X7R, 0603"
C35 C36: "CAP, CERM, 2200 pF, 50 V, +/- 10%, X7R, 0402"
CF1: "CAP, CERM, 0.1 µF, 25 V, +/- 10%, X7R, 0805"
D1: "LED, Red, SMD"
D2: "LED, Yellow, SMD"
E1: "2.4GHz PCB Antenna.  There is nothing to buy or mount."
FID1 FID2 FID3 FID4 FID5 FID6: "Fiducial mark.  There is nothing to buy or mount."
H1 H2 H3 H4: "Machine Screw, Round, #4-40 x 1/4, Nylon, Philips panhead"
H5 H6 H7 H8: "Standoff, Hex, 0.5\"L #4-40 Nylon"
J1 J2: "Header, 2.54 mm, 2x1, Gold, R/A, SMT"
J3 J4 J5: "CONN SOCKET RCPT .056-.065 30AU, Gold, TH"
J6: "Header, 2.54mm, 3x1, Gold, TH"
J7: "Jack, SMA, PCB, Gold, SMT"
J8: "Header, 50mil, 5x2, Gold, TH"
L1: "Inductor, Multilayer, Air Core, 15 nH, 0.3 A, 0.32 ohm, SMD"
L2: "Inductor, Multilayer, Air Core, 2 nH, 0.3 A, 0.1 ohm, SMD"
L3: "Ferrite Bead, 1500 ohm @ 100 MHz, 0.5 A, 0603"
L4: "Inductor, Multilayer, Ferrite, 10uH, 0.11A, 0.52 ohm, SMD"
Logo1: library part TI_Logo, "Texas Instrument Corporate Signature"
Logo2: library part Pb-Free
Logo3: library part FCC_disclaimer, "FCC_disclaimer"
Q1 Q2: "JFET, P-CH, -30 V, -0.015 A, SOT-23"
Q3: "MOSFET, P-CH, -20 V, -3.7 A, SOT-23"
R1 R3: "RES, 0, 5%, 0.1 W, 0603"
R2: "RES, 2.0 M, 5%, 0.125 W, 0805"
R4: "RES, 22 M, 10%, 0.125 W, 0805"
R5: "RES, 2.55 M, 1%, 0.125 W, 0805"
R6: "TRIMMER 2M OHM 0.25W SMD"
R7 R10 R12 RL1: "RES, 0, 5%, 0.125 W, 0805"
R8 R9: "RES, 4.75 k, 1%, 0.063 W, 0402"
R11 R13 R14 R15 R16: "RES, 0, 5%, 0.063 W, 0402"
R17: "RES, 54.9 k, 1%, 0.125 W, 0805"
R18: "RES, 196 k, 1%, 0.125 W, 0805"
R19: "RES, 10.0 k, 1%, 0.063 W, 0402"
R20 R21: "RES, 47.5 k, 1%, 0.063 W, 0402"
R22: "RES, 442, 1%, 0.125 W, 0805"
R23: "RES, 487, 1%, 0.125 W, 0805"
RF1: "RES, 1.78 M, 1%, 0.125 W, 0805"
RO1: "RES, 49.9 k, 1%, 0.1 W, 0603"
S1 S2: "SWITCH TACTILE SPST-NO 0.05A 12V"
SH-J1 SH-J2: "Shunt, 100mil, Gold plated, Black"
TP1 TP2 TP3 TP6: "Test Point, Miniature, Yellow, TH"
TP4 TP5: "Test Point, Multipurpose, Black, TH"
TP7 TP8: "Test Point, Miniature, SMT"
U1: "Precision 425 nA Nanopower Operational Amplifier, DBV0005A (SOT-5)"
U2: "Carbon Monoxide Detector, TH"
U3: "0.9-V to 6.5-V, Nanopower Comparator, DCK0005A"
U4: "Low-Power, Digital Temperature Sensor with Two-Wire Interface in WCSP, YFF0004AAAA"
U5: "Ultra low-power ARM Cortex M3 2.4 GHz Radio MCU, RSM0032B"
U6: "Nano-power System Timer for Power Gating, DDC0006A"
U7 U8 U9 U10: "ESD in 0402 Package with 10 pF Capacitance and 6 V Breakdown, 1 Channel, -40 to +125 degC, 2-pin X2SON (DPY), Green (RoHS & no Sb/Br)"
Y1: "Crystal, 24 MHz, 9 pF, SMD"
Y2: "Crystal, 32.768kHz, 12.5pF, SMD"
ZZ2 ZZ3 ZZ4: library part AssemblyNote

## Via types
v1: diameter 26, hole 10, Top Layer to Bottom Layer, tented both sides, 253 vias
v2: diameter 20, hole 10, Top Layer to Bottom Layer, tented both sides, 105 vias
v3: diameter 22, hole 10, Top Layer to Bottom Layer, tented both sides, 57 vias
v4: diameter 19.68, hole 7.87, Top Layer to Bottom Layer, 5 vias

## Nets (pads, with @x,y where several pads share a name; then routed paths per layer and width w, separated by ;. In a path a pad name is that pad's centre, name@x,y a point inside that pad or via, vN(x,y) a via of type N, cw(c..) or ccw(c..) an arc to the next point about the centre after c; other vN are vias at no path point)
CE: J4.1 R3.1 U2.2 | length 1117.3
  Top Layer w10: R3.1@1592.48,153.98 R3.1@1593.5,155
  Top Layer w20: U2.2@1087.36,153.98 U2.2@1382.64,153.98 ; R3.1@1583.5,153.98 U2.2@1382.64,153.98 ; J4.1@1607.68,680.43 1607.68,465.68 1382.64,240.64 U2.2@1382.64,153.98
CO_OUT: C4.1 C5.1 RO1.2 TP1.1 U3.3 U5.23 | length 1049.8
  Top Layer w7: v2(2785,809) 2788,806 2819,806 2855.63,842.63 U5.23@2880.2,842.63
  Top Layer w10: RO1.2@2455,873.5 C4.1@2515,873.5 2515,830 2500,815 TP1.1@2500,750 ; TP1.1@2500,748.5 2545,703.5 2545,460 2570.09,434.91 U3.3@2570.09,398.71 2570.09,344.97 C5.1@2568.12,343
  Signal Layer 2 w10: TP1.1@2500,750 2565,750 2580,735 2710,735 v2@2778.5,803.5
COMP_OUT: TP2.1 U3.4 U5.22 | length 545.9
  Top Layer w7.8: v2@2810,827 2823,840 2831,840 2849.38,858.38 U5.22@2880.2,858.38
  Top Layer w10: U3.4@2570.09,487.29 2612.29,487.29 TP2.1@2660,535
  Signal Layer 2 w10: TP2.1@2665,535 2665,540 2734,609 2734,725 2810,801 v2(2810,828)
DCDC_SW: L4.1 U5.18 | length 206.9
  Top Layer w7: L4.1@2673.26,921.31 U5.18@2880.2,921.31
GND: BT1.2 C1.1 C2.2 C3.2 C4.2 C6.2 C7.2 C8.2 C9.1 C10.1 C11.2 C12.1 C13.1 C14.2 C15.2 C16.2 C17.2 C18.2 C19.2 C20.1 C22.1 C23.2 C24.2 C25.1 C26.1 C27.2 C28.2 C29.2 C30.2 C31.2 C32.2 C33.1 C34.1 C35.1 C36.1 C37.1 C38.2 C39.2 C40.2 D1.2 D2.2 E1.2 E1.3 H1.1 H2.1 H3.1 H4.1 J6.3 J7.2 J7.3 J7.4 J7.5 J8.3 J8.5 J8.9 Q2.1 Q3.1 R6.3 R17.1 R18.2 R19.1 S1.1 S2.1 TP4.1 TP5.1 U1.2 U1.3 U3.2 U4.A2 U5.3 U5.7 U5.17 U5.20 U5.29 U5.33 U6.2 U7.2 U8.2 U9.2 U10.2 Y1.2 Y1.4 | length 1755.8
  Top Layer w7: v2(2950,690) 2962.87,702.87 U5.29@2962.87,807.2
  Top Layer w7.8: v1(1358,766) v1@1358,767 ; C34.1@2740,952.5 C34.1@2747.5,945 ; C33.1@2800,952.5 2801.5,953.99 C37.1@2801.5,1045 ; 2850,945 2857.88,937.12 U5.17@2880.2,937.12 ; U5.20@2880.2,889.87 2947.13,889.87 v4(2955,882) ; U5.29@2962.87,807.2 U5.33@2962.87,874.13 ; U5.3@3029.8,858.38 2978.62,858.38 U5.33@2962.87,874.13 ; U5.7@3029.8,921.37 2994.37,921.37 v4(2955,882) ; C32.2@3058.62,1035 3060,1036.38 v3(3060,1060) ; v4(2955,882) U5.33@2962.87,874.13
  Top Layer w10: R17.1@2048.94,1364.68 2058.94,1354.69 U6.2@2214.8,1354.69 ; C3.2@2105,913.62 2135.51,944.13 U1.2@2195,944.13 ; C34.1@2747.5,945 2850,945
  Top Layer w12: C40.2@2900,685.5 2903,682.5 v2(2903,666)
  Top Layer w15: Y1.2@2996.81,628.19 Y1.4@3055,570
  Top Layer w20: v2(2808,652) 2808,682 C30.2@2815,689 ; C31.2@2865,706.87 2865,704 v2(2903,666) ; Y1.2@2990,630 v3(2990,661.81) ; 3176.89,708.11 3255.64,708.11 3255.64,774.36 ; 3181.89,471.89 3255.64,471.89 v2@3255.64,410.64 ; 3460.36,415.36 3460.36,471.89 v2@3536.89,471.89 ; 3460.36,764.64 3460.36,708.11 3533.11,708.11
  other v1: 508,66 608,66 708,66 808,66 908,66 3208,66 3308,66 3408,66 3508,66 458,166 558,166 958,166 1758,166 1858,166 1958,166 2058,166 2158,166 2258,166 2358,166 2458,166 3058,166 408,266 508,266 608,266 708,266 3108,266 3208,266 258,366 358,366 458,366 558,366 658,366 758,366 958,366 1058,366 1158,366 1258,366 1458,366 1558,366 1658,366 1958,366 2058,366 2158,366 3058,366 3158,366 108,466 208,466 308,466 408,466 508,466 608,466 708,466 908,466 1008,466 1108,466 1208,466 1408,466 1508,466 1708,466 2308,466 2708,466 158,566 258,566 358,566 458,566 558,566 658,566 758,566 958,566 1058,566 1258,566 1358,566 1458,566 1558,566 1658,566 1758,566 2058,566 2258,566 2358,566 2458,566 3458,566 108,666 308,666 408,666 508,666 608,666 708,666 908,666 1008,666 1108,666 1308,666 1408,666 1508,666 1708,666 2008,666 2108,666 2308,666 358,766 458,766 558,766 658,766 758,766 958,766 1058,766 1258,766 1458,766 1558,766 1658,766 1758,766 1958,766 2258,766 308,866 408,866 508,866 608,866 708,866 1008,866 1108,866 1308,866 1408,866 1508,866 1608,866 1708,866 258,966 458,966 558,966 658,966 758,966 858,966 958,966 1058,966 1258,966 1458,966 1558,966 1658,966 1758,966 1858,966 2058,966 2558,966 208,1066 408,1066 508,1066 608,1066 708,1066 808,1066 908,1066 1008,1066 1108,1066 1308,1066 1408,1066 1508,1066 1608,1066 1808,1066 2108,1066 2208,1066 2408,1066 2508,1066 3408,1066 158,1166 458,1166 558,1166 658,1166 758,1166 858,1166 2358,1166 2458,1166 2558,1166 3058,1166 3158,1166 3358,1166 3458,1166 108,1266 208,1266 908,1266 1008,1266 1108,1266 1708,1266 1808,1266 1908,1266 2208,1266 2408,1266 2508,1266 2808,1266 3008,1266 3408,1266 3508,1266 558,1366 658,1366 758,1366 858,1366 958,1366 1058,1366 1158,1366 1258,1366 1358,1366 1458,1366 1558,1366 1658,1366 1758,1366 1858,1366 1958,1366 2758,1366 2858,1366 3058,1366 408,1466 508,1466 608,1466 708,1466 808,1466 908,1466 1008,1466 1108,1466 1208,1466 1308,1466 1408,1466 1508,1466 1608,1466 1708,1466 1808,1466 1908,1466 2008,1466 2108,1466 2208,1466 2408,1466 2508,1466 2608,1466 2708,1466 2908,1466 3208,1466 458,1566 558,1566 658,1566 758,1566 858,1566 958,1566 1058,1566 1158,1566 1258,1566 1358,1566 1458,1566 1558,1566 1658,1566 1958,1566 2058,1566 2158,1566 2258,1566 2358,1566 2458,1566 2558,1566 2658,1566 2758,1566 3558,1566
  other v2: 3505,120 3580,120 3580,170 3580,220 3580,270 3580,320 3530,370 3580,370 3205,420 3255,420 3305,420 3505,420 3580,420 3330,470 3380,470 3530,470 3580,470 3095,505 3125,505 3315,520 3355,520 3401,520 3580,520 3125,535 3285,570 3430,570 3530,570 3580,570 3580,620 3530,670 3580,670 3315,720 3400,720 3580,720 3100,750 3130,750 3155,770 3205,770 3305,770 3405,770 3480,770 3530,770 3580,770 3130,870 3180,870 3230,870 3280,870 3330,870 3380,870 3430,870 3480,870 3530,870 3580,870 3300,915 3355,920 3405,920 3455,920 3505,920 3580,920 3300,945 3330,970 3380,970 3430,970 3480,970 3530,970 3580,970 3300,975 3255,1020 3305,1020 3355,1020 3405,1020 3455,1020 3505,1020 3580,1020 3230,1070 3280,1070 3330,1070 3480,1070 3530,1070 3580,1070 3580,1120 3580,1170 3580,1220 3580,1270 3580,1320 3580,1370
  other v3: 2505,55 2910,55 1550,195 2450,375 2405,430 1810,445 1850,495 2340,515 1985,575 2175,580 2135,630 1985,700 2115,700 2060,785 2175,795 2090,815 2195,910 2075,915 2515,975 260,1040 130,1070 1840,1095 260,1100 240,1170 240,1230 380,1370 470,1370 2050,1405 2130,1405 3045,1445
  other v4: 2955,836.72 2909.72,882 3000.28,882 2955,927.28
I2C_SCL: R8.1 R10.2 U4.B2 U5.24 | length 2854.7
  Top Layer w7: v2(2855,785) 2855,820 2861.88,826.88 U5.24@2880.2,826.88
  Top Layer w8: R8.1@876.57,619.17 v3(876.57,640) U4.B2@876.57,677.05
  Top Layer w10: R8.1@872.32,614.92 R8.1@876.57,619.17
  Signal Layer 2 w10: v3(876.57,640) 876.57,348.43 957,268 2628,268 2785,425 2785,714 v2@2856,785
  Bottom Layer w10: R10.2@2700,380 v3(2740,380)
I2C_SDA: R9.1 R12.2 U4.B1 U5.25 | length 3002.8
  Top Layer w7: v2@2876.82,807.2 U5.25@2899.88,807.2
  Top Layer w8: v3@827.05,677.05 U4.B1@860,677.05
  Top Layer w10: R9.1@818.7,661.3 818.7,668.7 v3@827.05,677.05
  Signal Layer 2 w10: v3(838,677) 838,322 934,226 ; 935,226 2656,226 2835,405 2835,730 2880,775 v2(2880,805)
  Bottom Layer w10: R12.2@2835,360 v3@2835,404
  other v3: 2835,410
JTAG_TCK: J8.4 U5.14 U8.1 | length 628.8
  Top Layer w7.8: 2915,1015 2915,1005 2931.38,988.62 U5.14@2931.38,956.8
  Top Layer w10: 2915,1015 2915,1315 3009.25,1409.25 3009.25,1444.25 U8.1@3009.25,1469.69 3008.94,1470 J8.4@3008.94,1539.69
JTAG_TMS: J8.2 U5.13 U7.1 | length 744.4
  Top Layer w7.8: 2935,1022 2935,1010 2947.13,997.87 U5.13@2947.13,956.8
  Top Layer w10: 2935,1022 2935,1290 3128.94,1483.94 U7.1@3128.94,1540 3059.25,1540 J8.2@3058.94,1539.69 J8.2@3058.94,1533.94
NetBT1_1: BT1.1 Q3.3
NetC2_1: C2.1 Q1.2 R1.2 RL1.1 | length 655.1
  Top Layer w10: Q1.2@1867.24,647.76 1867.24,760 1860,767.24 1860,865 1930,935 RL1.1@1995,935
  Top Layer w20: R1.2@1926.5,1145 1926.5,1097.87 C2.1@1923.62,1095 1975,1095 1995,1075 RL1.1@1995,935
